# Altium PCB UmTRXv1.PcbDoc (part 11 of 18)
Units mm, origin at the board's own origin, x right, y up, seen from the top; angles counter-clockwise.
Board outline 172 x 113 mm, 6 copper layers (Top Layer, GND, MidLayer1, Mid-Layer 2, InternalPlane2, Bottom Layer); 766 components, 613 nets, 3008 pads, 1360 vias.
Unrouted connection lines stored in the file: 2.
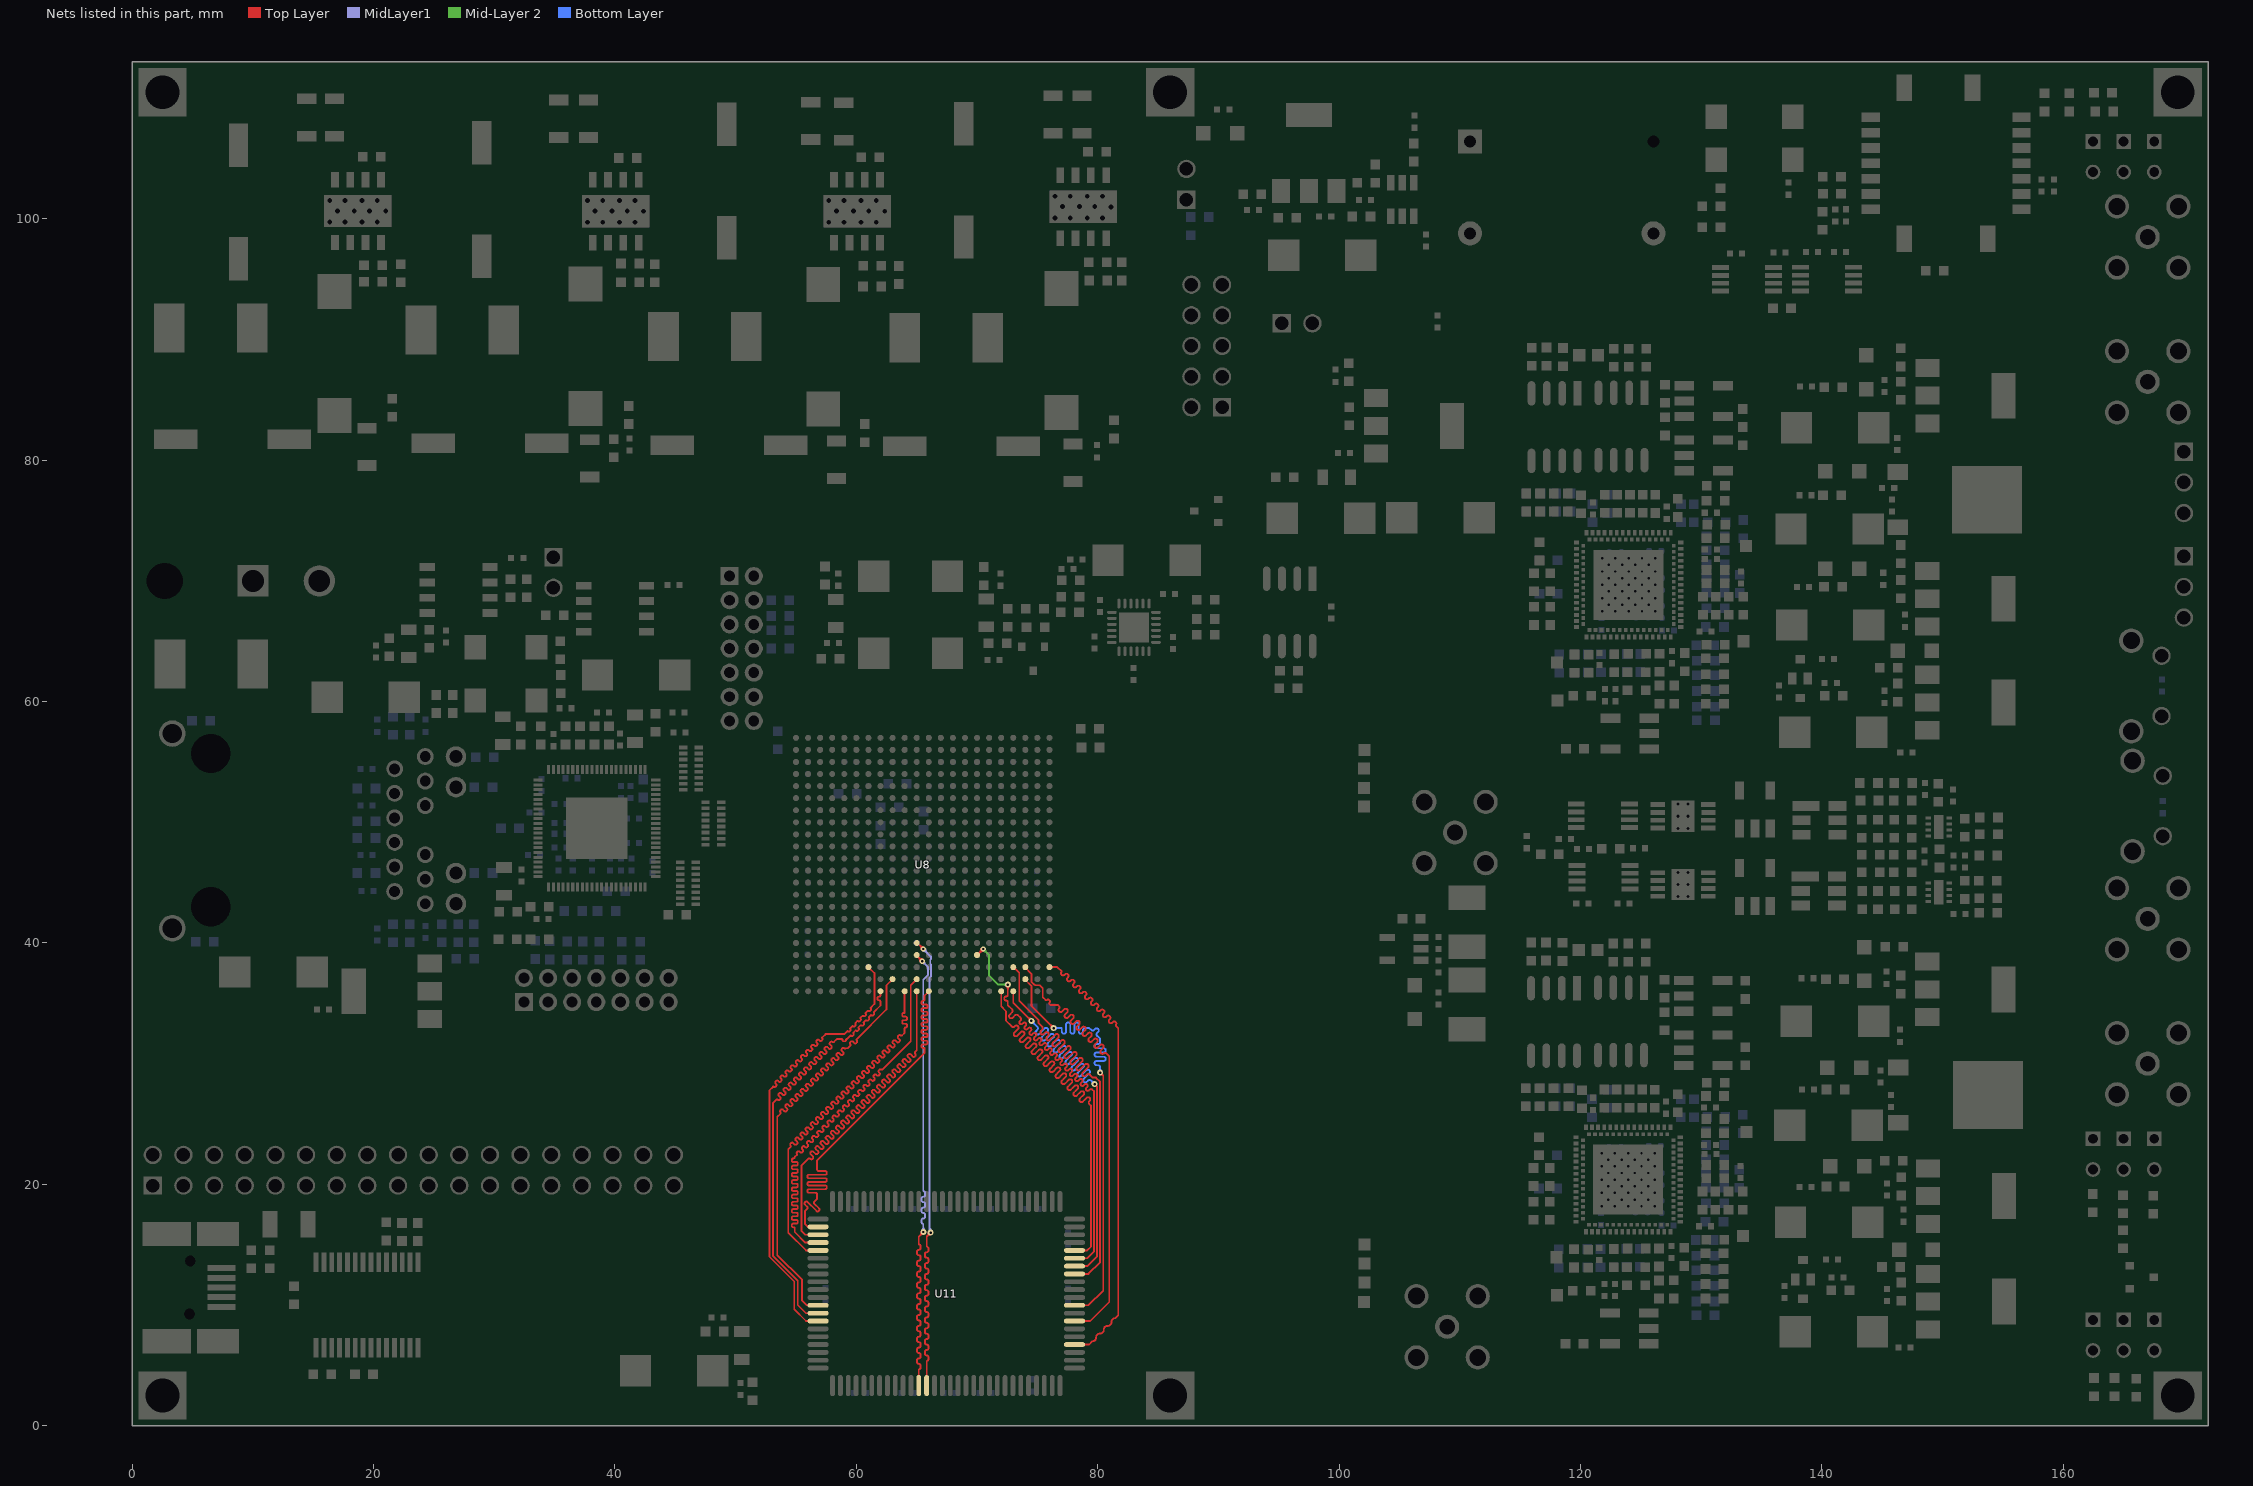
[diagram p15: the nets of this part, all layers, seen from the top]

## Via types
v1: diameter 0.45, hole 0.2, Top Layer to Bottom Layer, tented both sides, 554 vias
v2: diameter 0.5, hole 0.2, Top Layer to Bottom Layer, tented both sides, 468 vias
v3: diameter 0.7, hole 0.3, Top Layer to Bottom Layer, tented both sides, 206 vias
v4: diameter 0.4, hole 0.2, Top Layer to Bottom Layer, tented both sides, 82 vias
v5: diameter 0.8, hole 0.3, Top Layer to Bottom Layer, tented both sides, 16 vias
v6: diameter 0.6, hole 0.25, Top Layer to Bottom Layer, tented both sides, 16 vias
v7: diameter 0.5, hole 0.3, Top Layer to Bottom Layer, tented both sides, 8 vias
v8: diameter 0.7, hole 0.3, Top Layer to Bottom Layer, 4 vias
v9: diameter 0.6, hole 0.3, Top Layer to Bottom Layer, tented both sides, 4 vias
v10: diameter 0.5, hole 0.2, Top Layer to Bottom Layer, 2 vias

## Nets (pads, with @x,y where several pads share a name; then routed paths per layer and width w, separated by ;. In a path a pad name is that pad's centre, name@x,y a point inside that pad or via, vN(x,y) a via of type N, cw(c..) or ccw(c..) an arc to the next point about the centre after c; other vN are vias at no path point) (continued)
RAM_A13: U8.C16 U11.44 | length 40.9
  Top Layer w0.15: 54.158,29.2 54.179,29.179 54.2,29.158 cw(c54.115,29.073) 54.2,28.988 54.158,28.946 cw(c54.073,29.03) 53.988,28.946 53.946,28.988 ccw(c53.861,28.903) 53.776,28.988 53.733,28.946 ccw(c53.818,28.861) 53.733,28.776 53.776,28.733 cw(c53.691,28.649) 53.776,28.564 53.733,28.521 cw(c53.649,28.606) 53.564,28.521 53.521,28.564 ccw(c53.436,28.479) 53.352,28.564 53.309,28.521 ccw(c53.394,28.436) 53.309,28.352 53.352,28.309 cw(c53.267,28.224) 53.352,28.14 53.309,28.097 cw(c53.224,28.182) 53.139,28.097 ccw(c53.118,28.076) 53.097,28.097 52.8,27.8 52.8,13.996 54.85,11.946 54.85,9.65 55.825,8.675 U11.44@56.825,8.675 ; 54.157,29.2 cw(c54.242,29.285) 54.158,29.37 54.2,29.412 ; 54.2,29.412 cw(c54.285,29.327) 54.37,29.412 54.412,29.37 ccw(c54.497,29.455) 54.582,29.37 54.624,29.412 ; 54.624,29.836 cw(c54.709,29.752) 54.794,29.836 ; 54.624,29.836 54.582,29.794 ccw(c54.667,29.709) 54.582,29.624 54.624,29.582 cw(c54.539,29.497) 54.624,29.412 ; 54.794,29.836 54.836,29.794 ccw(c54.921,29.879) 55.006,29.794 55.049,29.836 ccw(c54.964,29.921) 55.049,30.006 ; 55.049,30.006 55.006,30.049 cw(c55.091,30.133) 55.006,30.218 55.049,30.261 ; 55.049,30.261 cw(c55.133,30.176) 55.218,30.261 55.261,30.218 ccw(c55.346,30.303) 55.43,30.218 55.473,30.261 ccw(c55.388,30.346) 55.473,30.43 55.43,30.473 cw(c55.515,30.558) 55.43,30.642 55.473,30.685 cw(c55.558,30.6) 55.643,30.685 55.685,30.643 ccw(c55.77,30.727) 55.855,30.642 55.897,30.685 ccw(c55.812,30.77) 55.897,30.855 55.876,30.876 55.855,30.897 cw(c55.94,30.982) 55.855,31.067 55.897,31.109 cw(c55.982,31.024) 56.067,31.109 56.109,31.067 ccw(c56.194,31.152) 56.279,31.067 56.321,31.109 ccw(c56.237,31.194) 56.321,31.279 56.279,31.321 cw(c56.364,31.406) 56.279,31.491 56.321,31.534 cw(c56.406,31.449) 56.491,31.534 56.534,31.491 ccw(c56.618,31.576) 56.703,31.491 56.746,31.534 ccw(c56.661,31.618) 56.746,31.703 56.703,31.746 cw(c56.788,31.831) 56.703,31.915 56.746,31.958 cw(c56.83,31.873) 56.915,31.958 56.958,31.915 ccw(c57.043,32) 57.127,31.915 57.17,31.958 ccw(c57.085,32.043) 57.17,32.127 cw(c57.191,32.149) 57.17,32.17 57.45,32.45 59,32.45 59.235,32.685 cw(c59.256,32.664) 59.277,32.685 ccw(c59.362,32.77) 59.447,32.685 59.489,32.727 ccw(c59.405,32.812) 59.489,32.897 cw(c59.511,32.918) 59.489,32.939 59.659,33.109 ; 59.659,33.109 cw(c59.68,33.088) 59.702,33.109 ccw(c59.786,33.194) 59.871,33.109 59.914,33.152 ccw(c59.829,33.236) 59.914,33.321 cw(c59.935,33.342) 59.914,33.364 60.083,33.533 cw(c60.105,33.512) 60.126,33.533 ccw(c60.211,33.618) 60.295,33.533 60.338,33.576 ccw(c60.253,33.661) 60.338,33.746 cw(c60.359,33.767) 60.338,33.788 60.508,33.958 cw(c60.529,33.936) 60.55,33.958 ccw(c60.635,34.042) 60.72,33.958 60.762,34 ccw(c60.677,34.085) 60.762,34.17 cw(c60.783,34.191) 60.762,34.212 60.932,34.382 cw(c60.953,34.361) 60.974,34.382 ccw(c61.059,34.467) 61.144,34.382 ; U8.C16@61,38 61.5,37.5 61.5,34.95 61.186,34.636 ccw(c61.208,34.615) 61.186,34.594 cw(c61.102,34.509) 61.186,34.424 61.144,34.382
RAM_A14: U8.A13 U11.35 | length 40.9
  Top Layer w0.15: 54.549,23.382 ccw(c54.634,23.297) 54.549,23.213 cw(c54.493,23.156) 54.549,23.099 54.35,22.9 54.35,16 55.825,14.525 U11.35@56.825,14.525 ; 54.549,23.382 54.592,23.425 cw(c54.677,23.34) 54.761,23.425 54.818,23.368 54.875,23.312 ccw(c54.96,23.396) 55.044,23.311 55.087,23.354 ccw(c55.002,23.439) 55.087,23.524 54.974,23.637 ; 54.974,23.637 cw(c55.059,23.722) 54.974,23.806 ; 54.974,23.807 55.016,23.849 cw(c55.101,23.764) 55.186,23.849 55.242,23.792 55.299,23.736 ccw(c55.384,23.821) 55.469,23.736 55.511,23.778 ccw(c55.426,23.863) 55.511,23.948 55.455,24.005 55.398,24.061 cw(c55.483,24.146) 55.398,24.231 ; 55.398,24.231 55.44,24.273 cw(c55.525,24.188) 55.61,24.273 55.667,24.217 55.723,24.16 ccw(c55.808,24.245) 55.893,24.16 55.935,24.203 ccw(c55.851,24.287) 55.935,24.372 55.879,24.429 55.822,24.485 cw(c55.907,24.57) 55.822,24.655 55.865,24.698 cw(c55.95,24.613) 56.034,24.698 56.091,24.641 56.148,24.584 ccw(c56.232,24.669) 56.317,24.584 56.36,24.627 ; 56.36,24.627 ccw(c56.275,24.712) 56.36,24.797 56.303,24.853 56.247,24.91 cw(c56.331,24.995) 56.246,25.079 56.289,25.122 cw(c56.374,25.037) 56.459,25.122 56.515,25.065 56.572,25.009 ccw(c56.657,25.094) 56.741,25.009 56.784,25.051 ; 56.784,25.051 ccw(c56.699,25.136) 56.784,25.221 56.671,25.334 cw(c56.756,25.419) 56.671,25.504 56.713,25.546 cw(c56.798,25.461) 56.883,25.546 56.94,25.49 56.996,25.433 ccw(c57.081,25.518) 57.166,25.433 ; 57.166,25.433 57.208,25.475 ccw(c57.123,25.56) 57.208,25.645 57.152,25.702 57.095,25.758 cw(c57.18,25.843) 57.095,25.928 57.137,25.97 cw(c57.222,25.885) 57.307,25.97 57.364,25.914 57.42,25.857 ccw(c57.505,25.942) 57.59,25.857 ; 57.59,25.857 57.632,25.9 ccw(c57.548,25.984) 57.633,26.069 57.576,26.126 57.519,26.182 cw(c57.604,26.267) 57.519,26.352 57.562,26.395 cw(c57.647,26.31) 57.731,26.395 57.788,26.338 57.845,26.281 ccw(c57.929,26.366) 58.014,26.281 58.057,26.324 ccw(c57.972,26.409) 58.057,26.494 58,26.55 57.944,26.607 cw(c58.028,26.692) 57.943,26.776 57.986,26.819 ; 57.986,26.819 cw(c58.071,26.734) 58.156,26.819 58.212,26.762 58.269,26.706 ccw(c58.354,26.791) 58.438,26.706 58.481,26.748 ccw(c58.396,26.833) 58.481,26.918 58.424,26.974 58.368,27.031 cw(c58.453,27.116) 58.368,27.201 58.41,27.243 ; 58.41,27.243 cw(c58.495,27.158) 58.58,27.243 58.637,27.187 58.693,27.13 ccw(c58.778,27.215) 58.863,27.13 58.905,27.172 ccw(c58.82,27.257) 58.905,27.342 58.849,27.399 58.792,27.455 cw(c58.877,27.54) 58.792,27.625 58.835,27.667 cw(c58.919,27.583) 59.004,27.667 59.061,27.611 59.117,27.554 ccw(c59.202,27.639) 59.287,27.554 59.33,27.597 ccw(c59.245,27.682) 59.33,27.766 ; 59.33,27.766 59.273,27.823 59.216,27.88 cw(c59.301,27.964) 59.216,28.049 59.259,28.092 cw(c59.344,28.007) 59.428,28.092 59.542,27.979 ; 59.542,27.978 ccw(c59.627,28.063) 59.711,27.978 ; 59.711,27.979 59.754,28.021 ccw(c59.669,28.106) 59.754,28.191 59.697,28.247 59.641,28.304 cw(c59.726,28.389) 59.64,28.473 59.683,28.516 cw(c59.768,28.431) 59.853,28.516 59.909,28.459 59.966,28.403 ccw(c60.051,28.488) 60.135,28.403 ; 60.136,28.403 60.178,28.445 ; 60.178,28.445 ccw(c60.093,28.53) 60.178,28.615 60.121,28.671 60.065,28.728 cw(c60.15,28.813) 60.065,28.898 60.107,28.94 cw(c60.192,28.855) 60.277,28.94 60.334,28.884 60.39,28.827 ccw(c60.475,28.912) 60.56,28.827 60.602,28.869 ; 60.602,28.87 ccw(c60.517,28.954) 60.602,29.039 60.546,29.096 60.489,29.152 cw(c60.574,29.237) 60.489,29.322 60.532,29.364 cw(c60.616,29.28) 60.701,29.364 60.758,29.308 60.814,29.251 ccw(c60.899,29.336) 60.984,29.251 61.027,29.294 ccw(c60.942,29.379) 61.027,29.463 60.97,29.52 60.913,29.577 cw(c60.998,29.661) 60.913,29.746 60.956,29.789 cw(c61.041,29.704) 61.125,29.789 61.239,29.676 ccw(c61.324,29.76) 61.408,29.675 61.451,29.718 ccw(c61.366,29.803) 61.451,29.888 61.394,29.944 61.338,30.001 ; 61.338,30.001 cw(c61.423,30.086) 61.338,30.171 61.38,30.213 cw(c61.465,30.128) 61.55,30.213 61.606,30.156 61.663,30.1 ccw(c61.748,30.185) 61.833,30.1 61.875,30.142 ccw(c61.79,30.227) 61.875,30.312 61.819,30.369 61.762,30.425 cw(c61.847,30.51) 61.762,30.595 ; 61.762,30.595 61.804,30.637 cw(c61.889,30.552) 61.974,30.637 ; 61.974,30.637 62.031,30.581 62.087,30.524 ccw(c62.172,30.609) 62.257,30.524 62.299,30.567 ccw(c62.215,30.651) 62.299,30.736 62.243,30.793 62.186,30.849 cw(c62.271,30.934) 62.186,31.019 62.229,31.062 cw(c62.314,30.977) 62.398,31.062 62.455,31.005 62.512,30.948 ccw(c62.596,31.033) 62.681,30.948 62.724,30.991 ; 62.724,30.991 ccw(c62.639,31.076) 62.724,31.16 62.667,31.217 62.61,31.274 cw(c62.695,31.358) 62.61,31.443 62.653,31.486 cw(c62.738,31.401) 62.823,31.486 62.879,31.429 62.936,31.373 ccw(c63.021,31.457) 63.105,31.372 63.148,31.415 ; 63.148,31.415 ccw(c63.063,31.5) 63.148,31.585 63.091,31.641 63.035,31.698 cw(c63.12,31.783) 63.035,31.868 63.077,31.91 cw(c63.162,31.825) 63.247,31.91 63.303,31.853 63.36,31.797 ccw(c63.445,31.882) 63.53,31.797 ; 63.53,31.797 63.572,31.839 ccw(c63.487,31.924) 63.572,32.009 63.516,32.066 63.459,32.122 cw(c63.544,32.207) 63.459,32.292 63.501,32.334 cw(c63.586,32.249) 63.671,32.334 ccw(c63.728,32.391) 63.784,32.334 64,32.55 64,32.92 cw(c64.08,32.92) 64.08,33 ccw(c64.08,33.12) 64.2,33.12 64.2,33.18 ccw(c64.08,33.18) 64.08,33.3 63.92,33.3 cw(c63.92,33.42) 63.8,33.42 63.8,33.48 cw(c63.92,33.48) 63.92,33.6 64.08,33.6 ccw(c64.08,33.72) 64.2,33.72 64.2,33.78 ccw(c64.08,33.78) 64.08,33.9 63.92,33.9 cw(c63.92,34.02) 63.8,34.02 63.8,34.08 cw(c63.92,34.08) 63.92,34.2 63.95,34.2 ccw(c63.95,34.25) 64,34.25 U8.A13@64,36
RAM_A15: U8.B12 U11.34 | length 41.3
  Top Layer w0.15: 55.552,22.709 55.509,22.667 cw(c55.424,22.752) 55.339,22.667 55.297,22.709 ccw(c55.212,22.625) 55.127,22.709 55.085,22.667 ccw(c55.17,22.582) 55.085,22.497 cw(c55.064,22.476) 55.085,22.455 54.9,22.27 cw(c54.78,22.27) 54.78,22.15 54.77,22.15 ccw(c54.77,22.03) 54.65,22.03 54.65,21.97 ccw(c54.77,21.97) 54.77,21.85 55.03,21.85 cw(c55.03,21.73) 55.15,21.73 55.15,21.67 cw(c55.03,21.67) 55.03,21.55 54.77,21.55 ccw(c54.77,21.43) 54.65,21.43 54.65,21.37 ccw(c54.77,21.37) 54.77,21.25 55.03,21.25 cw(c55.03,21.13) 55.15,21.13 55.15,21.07 cw(c55.03,21.07) 55.03,20.95 54.77,20.95 ccw(c54.77,20.83) 54.65,20.83 54.65,20.77 ccw(c54.77,20.77) 54.77,20.65 55.03,20.65 cw(c55.03,20.53) 55.15,20.53 55.15,20.47 cw(c55.03,20.47) 55.03,20.35 54.77,20.35 ccw(c54.77,20.23) 54.65,20.23 54.65,20.17 ccw(c54.77,20.17) 54.77,20.05 55.03,20.05 cw(c55.03,19.93) 55.15,19.93 55.15,19.87 cw(c55.03,19.87) 55.03,19.75 54.77,19.75 ccw(c54.77,19.63) 54.65,19.63 54.65,19.57 ccw(c54.77,19.57) 54.77,19.45 55.03,19.45 cw(c55.03,19.33) 55.15,19.33 55.15,19.27 cw(c55.03,19.27) 55.03,19.15 54.77,19.15 ccw(c54.77,19.03) 54.65,19.03 54.65,18.97 ccw(c54.77,18.97) 54.77,18.85 55.03,18.85 cw(c55.03,18.73) 55.15,18.73 55.15,18.67 cw(c55.03,18.67) 55.03,18.55 54.77,18.55 ccw(c54.77,18.43) 54.65,18.43 54.65,18.37 ccw(c54.77,18.37) 54.77,18.25 55.03,18.25 cw(c55.03,18.13) 55.15,18.13 55.15,18.07 cw(c55.03,18.07) 55.03,17.95 54.77,17.95 ccw(c54.77,17.83) 54.65,17.83 54.65,17.77 ccw(c54.77,17.77) 54.77,17.65 55.03,17.65 cw(c55.03,17.53) 55.15,17.53 55.15,17.47 cw(c55.03,17.47) 55.03,17.35 54.77,17.35 ccw(c54.77,17.23) 54.65,17.23 54.65,17.17 ccw(c54.77,17.17) 54.77,17.05 55.03,17.05 cw(c55.03,16.93) 55.15,16.93 55.15,16.87 cw(c55.03,16.87) 55.03,16.75 54.77,16.75 ccw(c54.77,16.63) 54.65,16.63 54.65,16.57 ccw(c54.77,16.57) 54.77,16.45 54.78,16.45 cw(c54.78,16.33) 54.9,16.33 54.9,16.05 55.775,15.175 U11.34@56.825,15.175 ; 55.552,23.134 55.509,23.091 ccw(c55.594,23.006) 55.509,22.922 55.552,22.879 cw(c55.467,22.794) 55.552,22.71 ; 55.552,23.134 cw(c55.636,23.049) 55.721,23.134 55.764,23.091 ccw(c55.849,23.176) 55.933,23.091 55.976,23.134 ccw(c55.891,23.219) 55.976,23.303 55.933,23.346 cw(c56.018,23.431) 55.933,23.515 55.976,23.558 cw(c56.061,23.473) 56.145,23.558 56.188,23.515 ccw(c56.273,23.6) 56.357,23.515 56.4,23.558 ccw(c56.315,23.643) 56.4,23.727 56.379,23.749 56.358,23.77 cw(c56.442,23.855) 56.358,23.94 56.4,23.982 cw(c56.485,23.897) 56.57,23.982 56.612,23.94 ccw(c56.697,24.025) 56.782,23.94 56.824,23.982 ccw(c56.739,24.067) 56.824,24.152 56.782,24.194 cw(c56.867,24.279) 56.782,24.364 56.824,24.406 cw(c56.909,24.322) 56.994,24.406 57.036,24.364 ccw(c57.121,24.449) 57.206,24.364 57.249,24.406 ccw(c57.164,24.491) 57.249,24.576 ; 57.206,24.788 ccw(c57.291,24.703) 57.206,24.619 57.249,24.576 ; 57.206,24.788 57.249,24.831 cw(c57.333,24.746) 57.418,24.831 57.461,24.788 ccw(c57.546,24.873) 57.63,24.788 57.673,24.831 ccw(c57.588,24.916) 57.673,25 57.63,25.043 cw(c57.715,25.128) 57.63,25.212 57.673,25.255 cw(c57.758,25.17) 57.843,25.255 57.885,25.213 ccw(c57.97,25.297) 58.055,25.212 ; 58.055,25.213 58.097,25.255 ccw(c58.012,25.34) 58.097,25.425 58.076,25.446 58.055,25.467 cw(c58.14,25.552) 58.055,25.637 58.097,25.679 cw(c58.182,25.594) 58.267,25.679 58.309,25.637 ccw(c58.394,25.722) 58.479,25.637 58.521,25.679 ccw(c58.437,25.764) 58.521,25.849 58.479,25.891 cw(c58.564,25.976) 58.479,26.061 ; 58.479,26.061 58.521,26.104 cw(c58.606,26.019) 58.691,26.104 58.734,26.061 ccw(c58.818,26.146) 58.903,26.061 ; 58.903,26.485 ccw(c58.988,26.4) 58.903,26.316 58.946,26.273 cw(c58.861,26.188) 58.946,26.103 58.903,26.061 ; 58.903,26.485 58.946,26.528 cw(c59.03,26.443) 59.115,26.528 59.158,26.485 ccw(c59.243,26.57) 59.327,26.485 59.37,26.528 ccw(c59.285,26.613) 59.37,26.697 59.327,26.74 cw(c59.412,26.825) 59.327,26.909 59.37,26.952 cw(c59.455,26.867) 59.54,26.952 59.582,26.91 ccw(c59.667,26.994) 59.752,26.909 59.794,26.952 ccw(c59.709,27.037) 59.794,27.122 59.752,27.164 cw(c59.837,27.249) 59.752,27.334 59.794,27.376 cw(c59.879,27.291) 59.964,27.376 60.006,27.334 ccw(c60.091,27.419) 60.176,27.334 60.218,27.376 ccw(c60.134,27.461) 60.218,27.546 60.176,27.588 cw(c60.261,27.673) 60.176,27.758 60.218,27.801 ; 60.219,27.801 cw(c60.303,27.716) 60.388,27.801 60.431,27.758 ccw(c60.515,27.843) 60.6,27.758 60.643,27.801 ; 60.643,27.801 ccw(c60.558,27.885) 60.643,27.97 60.6,28.013 cw(c60.685,28.098) 60.6,28.182 60.643,28.225 cw(c60.728,28.14) 60.812,28.225 ; 60.812,28.225 60.834,28.204 60.855,28.182 ccw(c60.94,28.267) 61.025,28.182 61.067,28.225 ; 61.067,28.225 ccw(c60.982,28.31) 61.067,28.395 61.025,28.437 cw(c61.109,28.522) 61.024,28.607 61.067,28.649 cw(c61.152,28.564) 61.237,28.649 61.279,28.607 ccw(c61.364,28.692) 61.449,28.607 61.491,28.649 ccw(c61.406,28.734) 61.491,28.819 61.449,28.861 cw(c61.534,28.946) 61.449,29.031 61.491,29.073 cw(c61.576,28.988) 61.661,29.074 61.703,29.031 ccw(c61.788,29.116) 61.873,29.031 61.915,29.073 ; 61.915,29.498 61.873,29.455 ccw(c61.958,29.37) 61.873,29.285 61.915,29.243 cw(c61.831,29.158) 61.916,29.073 ; 61.916,29.498 cw(c62,29.413) 62.085,29.498 ccw(c62.106,29.519) 62.128,29.498 64.5,31.87 64.5,36.5 U8.B12@65,37
RAM_A16: U8.A12 U11.33 | length 41.5
  Top Layer w0.15: 56.358,22.104 cw(c56.273,22.189) 56.188,22.105 56.181,22.112 ccw(c56.097,22.027) 56.012,22.112 55.45,21.55 55.45,16.15 55.775,15.825 U11.33@56.825,15.825 ; 56.358,22.105 56.401,22.147 ccw(c56.316,22.232) 56.401,22.317 56.309,22.409 56.217,22.501 cw(c56.302,22.585) 56.217,22.67 56.259,22.713 cw(c56.344,22.628) 56.429,22.713 56.613,22.529 ccw(c56.698,22.614) 56.782,22.529 56.825,22.571 ccw(c56.74,22.656) 56.825,22.741 56.641,22.925 cw(c56.726,23.01) 56.641,23.094 56.683,23.137 cw(c56.768,23.052) 56.853,23.137 57.037,22.953 ccw(c57.122,23.038) 57.207,22.953 ; 57.108,23.561 57.065,23.519 ccw(c57.15,23.434) 57.065,23.349 57.249,23.165 ; 57.108,23.561 cw(c57.193,23.476) 57.277,23.561 ; 57.207,22.953 57.249,22.996 ccw(c57.164,23.08) 57.249,23.165 ; 57.277,23.561 57.369,23.469 57.461,23.377 ; 57.461,23.377 ccw(c57.546,23.462) 57.631,23.377 57.673,23.42 ccw(c57.589,23.505) 57.673,23.59 57.49,23.773 ; 57.489,23.774 cw(c57.574,23.858) 57.49,23.943 57.532,23.986 cw(c57.617,23.901) 57.702,23.986 ; 57.702,23.986 57.886,23.802 ccw(c57.97,23.887) 58.055,23.802 58.098,23.844 ccw(c58.013,23.929) 58.098,24.014 58.006,24.106 57.914,24.198 ; 57.914,24.198 cw(c57.999,24.283) 57.914,24.367 ; 57.914,24.367 57.956,24.41 cw(c58.041,24.325) 58.126,24.41 ; 58.126,24.41 58.31,24.226 ccw(c58.395,24.311) 58.479,24.226 58.522,24.268 ccw(c58.437,24.353) 58.522,24.438 58.43,24.53 58.338,24.622 ; 58.338,24.622 cw(c58.423,24.707) 58.338,24.792 58.38,24.834 cw(c58.465,24.749) 58.55,24.834 58.734,24.65 ccw(c58.819,24.735) 58.904,24.65 58.946,24.693 ccw(c58.861,24.777) 58.946,24.862 ; 58.946,24.862 58.762,25.046 cw(c58.847,25.131) 58.762,25.216 58.805,25.258 cw(c58.89,25.173) 58.974,25.258 59.066,25.166 59.158,25.074 ; 59.158,25.074 ccw(c59.243,25.159) 59.328,25.074 59.37,25.117 ; 59.371,25.117 ccw(c59.286,25.202) 59.37,25.287 59.187,25.47 cw(c59.271,25.555) 59.187,25.64 59.229,25.683 cw(c59.314,25.598) 59.399,25.683 59.583,25.499 ccw(c59.667,25.584) 59.752,25.499 59.795,25.541 ccw(c59.71,25.626) 59.795,25.711 59.703,25.803 59.611,25.895 cw(c59.696,25.98) 59.611,26.064 59.653,26.107 cw(c59.738,26.022) 59.823,26.107 60.007,25.923 ccw(c60.092,26.008) 60.177,25.923 60.219,25.965 ; 60.219,25.966 ccw(c60.134,26.05) 60.219,26.135 60.127,26.227 60.035,26.319 cw(c60.12,26.404) 60.035,26.489 60.078,26.531 cw(c60.162,26.446) 60.247,26.531 60.431,26.347 ccw(c60.516,26.432) 60.601,26.347 60.643,26.39 ccw(c60.558,26.475) 60.643,26.559 60.459,26.743 cw(c60.544,26.828) 60.459,26.913 ; 60.459,26.913 60.502,26.955 cw(c60.587,26.871) 60.671,26.956 60.763,26.863 60.855,26.772 ccw(c60.94,26.856) 61.025,26.771 61.067,26.814 ccw(c60.983,26.899) 61.068,26.983 60.884,27.167 cw(c60.968,27.252) 60.884,27.337 60.926,27.38 cw(c61.011,27.295) 61.096,27.38 61.28,27.196 ccw(c61.364,27.281) 61.449,27.196 61.492,27.238 ccw(c61.407,27.323) 61.492,27.408 61.308,27.592 cw(c61.393,27.677) 61.308,27.761 61.35,27.804 cw(c61.435,27.719) 61.52,27.804 61.704,27.62 ccw(c61.789,27.705) 61.874,27.62 61.916,27.662 ccw(c61.831,27.747) 61.916,27.832 61.824,27.924 61.732,28.016 cw(c61.817,28.101) 61.732,28.186 61.775,28.228 cw(c61.859,28.143) 61.944,28.228 62.128,28.044 ccw(c62.213,28.129) 62.298,28.044 62.34,28.087 ccw(c62.255,28.172) 62.34,28.256 62.156,28.44 cw(c62.241,28.525) 62.156,28.61 62.199,28.652 cw(c62.284,28.568) 62.368,28.653 62.46,28.56 62.552,28.469 ccw(c62.637,28.553) 62.722,28.468 ; 62.722,28.469 62.765,28.511 ccw(c62.68,28.596) 62.765,28.681 62.581,28.865 cw(c62.666,28.949) 62.581,29.034 62.623,29.077 cw(c62.708,28.992) 62.793,29.077 62.885,28.985 62.977,28.893 ccw(c63.062,28.978) 63.146,28.893 63.189,28.935 ccw(c63.104,29.02) 63.189,29.105 63.005,29.289 cw(c63.09,29.374) 63.005,29.458 63.047,29.501 cw(c63.132,29.416) 63.217,29.501 63.401,29.317 ccw(c63.486,29.402) 63.57,29.317 ; 63.571,29.317 63.613,29.36 ccw(c63.528,29.444) 63.613,29.529 ; 63.613,29.529 63.521,29.621 63.429,29.713 cw(c63.514,29.798) 63.429,29.883 63.472,29.925 cw(c63.556,29.84) 63.641,29.925 63.825,29.741 ; 63.825,29.741 ccw(c63.91,29.826) 63.995,29.741 64.037,29.784 ccw(c63.952,29.869) 64.037,29.953 63.853,30.137 cw(c63.938,30.222) 63.853,30.307 63.896,30.349 ; 63.896,30.35 cw(c63.981,30.265) 64.066,30.349 64.249,30.166 ccw(c64.334,30.25) 64.419,30.165 64.462,30.208 ccw(c64.377,30.293) 64.462,30.378 64.278,30.562 ; 64.278,30.562 cw(c64.363,30.646) 64.278,30.731 64.32,30.774 cw(c64.405,30.689) 64.49,30.774 ; 64.49,30.774 64.582,30.682 64.674,30.59 ccw(c64.759,30.675) 64.843,30.59 64.886,30.632 ccw(c64.801,30.717) 64.886,30.802 64.879,30.809 cw(c64.964,30.894) 64.879,30.979 65,31.1 U8.A12@65,36
RAM_A17: U8.A11 U11.32 | length 41
  Top Layer w0.15: U11.32@56.825,16.475 55.975,16.475 55.75,16.7 55.75,17.8 55.925,17.975 ccw(c55.842,18.058) 55.925,18.14 55.735,18.33 cw(c55.82,18.415) 55.735,18.5 55.778,18.542 cw(c55.862,18.457) 55.947,18.542 56.701,17.789 ccw(c56.785,17.874) 56.87,17.789 56.913,17.831 ccw(c56.828,17.916) 56.913,18.001 56.517,18.397 cw(c56.602,18.482) 56.517,18.567 56.75,18.8 56.75,19.18 ccw(c56.63,19.18) 56.63,19.3 56.07,19.3 cw(c56.07,19.42) 55.95,19.42 55.95,19.48 cw(c56.07,19.48) 56.07,19.6 57.43,19.6 ccw(c57.43,19.72) 57.55,19.72 57.55,19.78 ccw(c57.43,19.78) 57.43,19.9 56.07,19.9 cw(c56.07,20.02) 55.95,20.02 55.95,20.08 cw(c56.07,20.08) 56.07,20.2 57.43,20.2 ccw(c57.43,20.32) 57.55,20.32 57.55,20.38 ccw(c57.43,20.38) 57.43,20.5 56.07,20.5 cw(c56.07,20.62) 55.95,20.62 55.95,20.68 cw(c56.07,20.68) 56.07,20.8 57.43,20.8 ccw(c57.43,20.92) 57.55,20.92 57.55,20.98 ccw(c57.43,20.98) 57.43,21.1 56.87,21.1 cw(c56.87,21.22) 56.75,21.22 56.75,22 65.65,30.9 65.65,31.3 65.52,31.3 cw(c65.52,31.42) 65.4,31.42 65.4,31.48 cw(c65.52,31.48) 65.52,31.6 65.78,31.6 ccw(c65.78,31.72) 65.9,31.72 65.9,31.78 ccw(c65.78,31.78) 65.78,31.9 65.52,31.9 cw(c65.52,32.02) 65.4,32.02 65.4,32.08 cw(c65.52,32.08) 65.52,32.2 65.78,32.2 ccw(c65.78,32.32) 65.9,32.32 65.9,32.38 ccw(c65.78,32.38) 65.78,32.5 65.52,32.5 cw(c65.52,32.62) 65.4,32.62 65.4,32.68 cw(c65.52,32.68) 65.52,32.8 65.78,32.8 ccw(c65.78,32.92) 65.9,32.92 65.9,32.98 ccw(c65.78,32.98) 65.78,33.1 65.52,33.1 cw(c65.52,33.22) 65.4,33.22 65.4,33.28 cw(c65.52,33.28) 65.52,33.4 65.78,33.4 ccw(c65.78,33.52) 65.9,33.52 65.9,33.58 ccw(c65.78,33.58) 65.78,33.7 65.52,33.7 cw(c65.52,33.82) 65.4,33.82 65.4,33.88 cw(c65.52,33.88) 65.52,34 65.78,34 ccw(c65.78,34.12) 65.9,34.12 65.9,34.18 ccw(c65.78,34.18) 65.78,34.3 65.52,34.3 cw(c65.52,34.42) 65.4,34.42 65.4,34.48 cw(c65.52,34.48) 65.52,34.6 65.78,34.6 ccw(c65.78,34.72) 65.9,34.72 65.9,34.78 ccw(c65.78,34.78) 65.78,34.9 65.52,34.9 cw(c65.52,35.02) 65.4,35.02 65.4,35.08 cw(c65.52,35.08) 65.52,35.2 65.53,35.2 ccw(c65.53,35.32) 65.65,35.32 65.65,35.65 U8.A11@66,36
RAM_A18: U8.C1 U11.84 | length 41
  Top Layer w0.15: U8.C1@76,38 76.65,38 77.004,37.646 cw(c76.986,37.629) 77.004,37.611 ccw(c77.127,37.487) 77.004,37.364 ccw(c77.127,37.487) 77.251,37.364 77.286,37.399 cw(c77.41,37.275) 77.534,37.399 cw(c77.41,37.275) 77.534,37.151 77.499,37.116 ccw(c77.622,36.992) 77.499,36.869 ccw(c77.622,36.992) 77.746,36.869 77.764,36.886 77.781,36.904 cw(c77.905,36.78) 78.029,36.904 cw(c77.905,36.78) 78.029,36.657 78.011,36.639 77.993,36.621 ccw(c78.117,36.497) 77.993,36.374 ccw(c78.117,36.497) 78.241,36.374 78.276,36.409 cw(c78.4,36.285) 78.524,36.409 cw(c78.4,36.285) 78.524,36.162 78.488,36.126 ccw(c78.612,36.002) 78.488,35.879 ccw(c78.612,36.002) 78.736,35.879 78.771,35.914 cw(c78.895,35.79) 79.019,35.914 cw(c78.895,35.79) 79.019,35.667 79.001,35.649 78.983,35.631 ccw(c79.107,35.507) 78.983,35.384 ccw(c79.107,35.507) 79.231,35.384 79.249,35.401 79.266,35.419 cw(c79.39,35.295) 79.514,35.419 cw(c79.39,35.295) 79.514,35.172 79.478,35.136 ccw(c79.602,35.012) 79.478,34.889 ccw(c79.602,35.012) 79.726,34.889 79.761,34.924 cw(c79.885,34.8) 80.009,34.924 cw(c79.885,34.8) 80.009,34.677 79.991,34.659 79.973,34.641 ccw(c80.097,34.518) 79.973,34.394 ccw(c80.097,34.518) 80.221,34.394 80.239,34.411 80.256,34.429 cw(c80.38,34.305) 80.504,34.429 cw(c80.38,34.305) 80.504,34.182 80.468,34.146 ccw(c80.592,34.023) 80.468,33.899 ccw(c80.592,34.023) 80.716,33.899 80.751,33.934 cw(c80.875,33.81) 80.999,33.934 cw(c80.875,33.81) 80.999,33.687 80.963,33.651 ccw(c81.087,33.528) 80.963,33.404 ccw(c81.087,33.528) 81.211,33.404 81.229,33.421 81.246,33.439 cw(c81.37,33.315) 81.494,33.439 cw(c81.37,33.315) 81.494,33.192 ccw(c81.511,33.174) 81.494,33.156 81.7,32.95 81.7,9.15 81.459,8.909 ccw(c81.444,8.606) 81.141,8.591 cw(c80.838,8.576) 80.823,8.273 ccw(c80.807,7.97) 80.505,7.955 cw(c80.202,7.939) 80.186,7.636 ccw(c80.171,7.334) 79.868,7.318 cw(c79.565,7.303) 79.55,7 79.275,6.725 U11.84@78.075,6.725
RAM_A19: U8.A15 U11.43 | length 40.8
  Top Layer w0.15: 54.04,27.973 53.998,27.931 ccw(c54.083,27.846) 53.998,27.761 54.055,27.705 54.111,27.648 cw(c54.026,27.563) 54.111,27.478 54.069,27.436 cw(c53.984,27.521) 53.899,27.436 53.842,27.492 53.786,27.549 ccw(c53.701,27.464) 53.616,27.549 53.574,27.507 ccw(c53.659,27.422) 53.574,27.337 53.687,27.224 cw(c53.602,27.139) 53.687,27.054 53.644,27.012 cw(c53.56,27.096) 53.475,27.012 ccw(c53.418,26.955) 53.362,27.012 53.1,26.75 53.1,14.05 55.15,12 55.15,10 55.825,9.325 U11.43@56.825,9.325 ; 54.041,27.973 cw(c54.125,27.888) 54.21,27.973 54.267,27.917 54.323,27.86 ccw(c54.408,27.945) 54.493,27.86 54.535,27.903 ccw(c54.451,27.987) 54.535,28.072 54.479,28.129 54.422,28.185 ; 54.422,28.186 cw(c54.507,28.27) 54.422,28.355 54.465,28.398 ; 54.465,28.398 cw(c54.55,28.313) 54.634,28.398 54.691,28.341 54.748,28.284 ccw(c54.832,28.369) 54.917,28.284 54.96,28.327 ; 54.96,28.327 ccw(c54.875,28.412) 54.96,28.497 54.903,28.553 54.847,28.61 cw(c54.931,28.695) 54.846,28.779 54.889,28.822 cw(c54.974,28.737) 55.059,28.822 55.115,28.765 55.172,28.709 ccw(c55.257,28.794) 55.341,28.709 55.384,28.751 ccw(c55.299,28.836) 55.384,28.921 ; 55.384,28.921 55.271,29.034 cw(c55.356,29.119) 55.271,29.204 55.313,29.246 cw(c55.398,29.161) 55.483,29.246 55.54,29.19 55.596,29.133 ccw(c55.681,29.218) 55.766,29.133 ; 55.766,29.133 55.808,29.175 ccw(c55.723,29.26) 55.808,29.345 55.752,29.402 55.695,29.458 cw(c55.78,29.543) 55.695,29.628 55.737,29.67 cw(c55.822,29.585) 55.907,29.67 55.964,29.614 56.02,29.557 ccw(c56.105,29.642) 56.19,29.557 ; 56.119,30.052 ccw(c56.204,29.967) 56.119,29.882 56.176,29.826 56.232,29.769 cw(c56.148,29.684) 56.232,29.6 56.19,29.557 ; 56.119,30.052 56.162,30.095 cw(c56.247,30.01) 56.331,30.095 56.388,30.038 56.445,29.981 ccw(c56.529,30.066) 56.614,29.981 56.657,30.024 ccw(c56.572,30.109) 56.657,30.194 56.6,30.25 56.544,30.307 cw(c56.628,30.392) 56.543,30.476 56.586,30.519 cw(c56.671,30.434) 56.756,30.519 56.812,30.462 56.869,30.406 ccw(c56.954,30.491) 57.038,30.406 57.081,30.448 ccw(c56.996,30.533) 57.081,30.618 57.024,30.674 56.968,30.731 cw(c57.053,30.816) 56.968,30.901 57.01,30.943 cw(c57.095,30.858) 57.18,30.943 57.237,30.887 57.293,30.83 ccw(c57.378,30.915) 57.463,30.83 57.505,30.872 ccw(c57.42,30.957) 57.505,31.042 57.449,31.099 57.392,31.155 cw(c57.477,31.24) 57.392,31.325 ; 57.392,31.325 57.435,31.367 cw(c57.519,31.283) 57.604,31.367 57.661,31.311 57.717,31.254 ccw(c57.802,31.339) 57.887,31.254 ; 57.816,31.749 ccw(c57.901,31.664) 57.816,31.58 57.873,31.523 57.93,31.466 cw(c57.845,31.382) 57.93,31.297 57.887,31.254 ; 57.816,31.749 57.859,31.792 cw(c57.944,31.707) 58.029,31.792 ccw(c58.085,31.848) 58.142,31.792 58.4,32.05 58.77,32.05 cw(c58.77,31.97) 58.85,31.97 ccw(c58.97,31.97) 58.97,31.85 59.03,31.85 ccw(c59.03,31.97) 59.15,31.97 cw(c59.23,31.97) 59.23,32.05 59.501,32.321 cw(c59.523,32.3) 59.544,32.321 ccw(c59.629,32.406) 59.714,32.321 59.756,32.364 ccw(c59.671,32.449) 59.756,32.534 cw(c59.777,32.555) 59.756,32.576 59.926,32.746 cw(c59.947,32.724) 59.968,32.746 ccw(c60.053,32.831) 60.138,32.746 60.18,32.788 ccw(c60.095,32.873) 60.18,32.958 cw(c60.201,32.979) 60.18,33 ; 60.18,33 60.35,33.17 cw(c60.371,33.149) 60.392,33.17 ccw(c60.477,33.255) 60.562,33.17 60.604,33.212 ccw(c60.52,33.297) 60.604,33.382 cw(c60.626,33.403) 60.604,33.424 60.774,33.594 cw(c60.795,33.573) 60.817,33.594 ccw(c60.901,33.679) 60.986,33.594 61.029,33.637 ccw(c60.944,33.721) 61.029,33.806 cw(c61.05,33.828) 61.029,33.849 61.198,34.018 ; 61.199,34.019 cw(c61.22,33.997) 61.241,34.018 ccw(c61.326,34.103) 61.411,34.018 61.453,34.061 ccw(c61.368,34.146) 61.453,34.231 cw(c61.474,34.252) 61.453,34.273 62,34.82 62,35.13 ccw(c61.88,35.13) 61.88,35.25 61.87,35.25 cw(c61.87,35.37) 61.75,35.37 61.75,35.43 cw(c61.87,35.43) 61.87,35.55 61.88,35.55 ccw(c61.88,35.67) 62,35.67 U8.A15@62,36
RAM_A20: U8.B14 U11.42 | length 40.9
  Top Layer w0.15: 54.56,26.993 ccw(c54.645,26.908) 54.56,26.823 54.617,26.767 54.673,26.71 cw(c54.588,26.625) 54.673,26.541 54.631,26.498 ; 54.56,26.993 54.603,27.035 cw(c54.687,26.951) 54.772,27.035 54.829,26.979 54.885,26.922 ccw(c54.97,27.007) 55.055,26.922 55.098,26.965 ccw(c55.013,27.05) 55.098,27.134 55.041,27.191 54.984,27.248 cw(c55.069,27.332) 54.984,27.417 ; 54.631,26.498 cw(c54.546,26.583) 54.461,26.498 54.405,26.555 54.348,26.611 ccw(c54.263,26.526) 54.178,26.611 54.136,26.569 ccw(c54.221,26.484) 54.136,26.399 54.192,26.342 54.249,26.286 cw(c54.164,26.201) 54.249,26.116 54.207,26.074 cw(c54.122,26.159) 54.037,26.074 53.924,26.187 ccw(c53.839,26.102) 53.754,26.187 53.712,26.144 ccw(c53.796,26.06) 53.712,25.975 cw(c53.655,25.918) 53.712,25.862 53.45,25.6 53.45,14.132 55.5,12.082 55.5,10.35 55.875,9.975 U11.42@56.825,9.975 ; 54.984,27.417 55.027,27.46 cw(c55.112,27.375) 55.197,27.46 55.253,27.403 55.31,27.347 ccw(c55.395,27.431) 55.479,27.346 55.522,27.389 ccw(c55.437,27.474) 55.522,27.559 55.465,27.615 55.409,27.672 cw(c55.494,27.757) 55.409,27.841 55.451,27.884 ; 55.451,27.884 cw(c55.536,27.799) 55.621,27.884 55.734,27.771 ccw(c55.819,27.856) 55.904,27.771 55.946,27.813 ; 55.875,28.308 55.833,28.266 ccw(c55.918,28.181) 55.833,28.096 55.89,28.04 55.946,27.983 cw(c55.861,27.898) 55.946,27.813 ; 55.876,28.308 cw(c55.96,28.223) 56.045,28.308 56.102,28.252 56.158,28.195 ccw(c56.243,28.28) 56.328,28.195 56.37,28.238 ; 56.37,28.238 ccw(c56.285,28.322) 56.37,28.407 56.314,28.464 56.257,28.52 cw(c56.342,28.605) 56.257,28.69 56.3,28.732 cw(c56.384,28.648) 56.469,28.733 56.526,28.676 56.582,28.619 ccw(c56.667,28.704) 56.752,28.619 56.795,28.662 ccw(c56.71,28.747) 56.795,28.831 56.738,28.888 56.681,28.945 cw(c56.766,29.029) 56.681,29.114 56.724,29.157 cw(c56.809,29.072) 56.894,29.157 56.95,29.1 57.007,29.044 ccw(c57.092,29.128) 57.176,29.043 57.219,29.086 ccw(c57.134,29.171) 57.219,29.256 57.162,29.312 57.106,29.369 cw(c57.191,29.454) 57.106,29.538 57.148,29.581 cw(c57.233,29.496) 57.318,29.581 57.374,29.524 57.431,29.468 ccw(c57.516,29.553) 57.601,29.468 57.643,29.51 ; 57.53,29.793 57.587,29.737 57.643,29.68 cw(c57.558,29.595) 57.643,29.51 ; 57.53,29.793 cw(c57.615,29.878) 57.53,29.963 57.572,30.005 ; 57.573,30.005 cw(c57.657,29.92) 57.742,30.005 57.799,29.949 57.855,29.892 ccw(c57.94,29.977) 58.025,29.892 58.067,29.935 ; 58.068,29.935 ccw(c57.983,30.019) 58.067,30.104 58.011,30.161 57.954,30.217 cw(c58.039,30.302) 57.954,30.387 57.997,30.43 cw(c58.082,30.345) 58.166,30.43 ; 58.166,30.43 58.223,30.373 58.28,30.316 ccw(c58.364,30.401) 58.449,30.316 58.492,30.359 ccw(c58.407,30.444) 58.492,30.528 58.379,30.642 cw(c58.463,30.727) 58.378,30.811 58.421,30.854 cw(c58.506,30.769) 58.591,30.854 58.647,30.797 58.704,30.741 ccw(c58.789,30.826) 58.873,30.741 58.916,30.783 ccw(c58.831,30.868) 58.916,30.953 58.859,31.009 58.803,31.066 cw(c58.888,31.151) 58.803,31.235 ; 58.803,31.236 58.845,31.278 cw(c58.93,31.193) 59.015,31.278 59.018,31.275 ccw(c59.071,31.329) 59.125,31.275 59.275,31.275 59.499,31.499 ccw(c59.443,31.556) 59.499,31.613 cw(c59.584,31.697) 59.499,31.782 59.542,31.825 cw(c59.627,31.74) 59.711,31.825 59.768,31.768 59.825,31.712 ccw(c59.91,31.796) 59.994,31.712 60.037,31.754 ccw(c59.952,31.839) 60.037,31.924 cw(c60.093,31.98) 60.037,32.037 62.5,34.5 62.5,36.5 U8.B14@63,37
RAM_BWN0: U8.C4 U11.93 | length 41.3
  Top Layer w0.15: U8.C4@73,38 73.05,38 73.5,37.55 73.5,35.199 75.1,33.599 75.1,33.35 75.394,33.056 cw(c75.27,32.932) 75.394,32.809 75.298,32.713 ccw(c75.422,32.589) 75.298,32.466 ccw(c75.422,32.589) 75.546,32.466 75.641,32.561 cw(c75.765,32.438) 75.889,32.561 cw(c75.765,32.438) 75.889,32.314 75.793,32.218 ccw(c75.917,32.094) 75.793,31.971 ccw(c75.917,32.094) 76.041,31.971 76.479,32.409 cw(c76.603,32.286) 76.727,32.409 cw(c76.603,32.286) 76.727,32.162 76.507,31.943 76.29,31.725 ccw(c76.414,31.602) 76.29,31.478 ccw(c76.414,31.602) 76.538,31.478 76.755,31.695 76.974,31.914 cw(c77.098,31.791) 77.222,31.914 cw(c77.098,31.791) 77.222,31.667 77.002,31.448 76.788,31.233 ccw(c76.912,31.109) 76.788,30.985 ccw(c76.912,31.109) 77.035,30.985 77.25,31.2 77.469,31.419 cw(c77.593,31.296) 77.717,31.419 cw(c77.593,31.296) 77.717,31.172 77.278,30.733 ccw(c77.402,30.609) 77.278,30.486 ccw(c77.402,30.609) 77.526,30.486 77.964,30.924 cw(c78.088,30.801) 78.212,30.924 cw(c78.088,30.801) 78.212,30.677 77.773,30.238 ccw(c77.897,30.115) 77.773,29.991 ccw(c77.897,30.115) 78.02,29.991 78.24,30.21 78.459,30.43 cw(c78.583,30.306) 78.707,30.43 cw(c78.583,30.306) 78.707,30.182 78.268,29.743 ccw(c78.392,29.62) 78.268,29.496 ccw(c78.392,29.62) 78.515,29.496 78.954,29.935 cw(c79.078,29.811) 79.202,29.935 cw(c79.078,29.811) 79.202,29.687 78.763,29.248 ccw(c78.887,29.125) 78.763,29.001 ; U11.93@78.075,12.575 79.225,12.575 80.2,13.55 80.2,28.499 79.85,28.849 79.601,28.849 79.354,29.096 ccw(c79.23,28.973) 79.106,29.096 79.01,29.001 cw(c78.887,29.125) 78.763,29.001
RAM_BWN1: U8.A4 U11.94 | length 43.6
  Top Layer w0.15: U8.A4@73,36 73,35.05 v2(74.5,33.55) ; v2@74.325,33.55 ccw(c73.903,33.55) 74.201,33.849 ccw(c74.5,34.147) v2@74.5,33.725 ; U11.94@78.075,13.225 79.125,13.225 79.95,14.05 79.95,28.1 ; v2(79.75,28.3) 79.95,28.1 ; v2@79.806,28.134 cw(c79.85,28) 79.95,28.1 ; v2@79.916,28.244 ccw(c80.05,28.2) 79.95,28.1
  Bottom Layer w0.15: v2@74.5,33.375 cw(c74.5,32.953) 74.799,33.251 cw(c75.097,33.55) v2@74.675,33.55 ; v2(74.5,33.55) 74.995,33.055 cw(c74.871,32.931) 74.995,32.807 74.89,32.702 ccw(c75.014,32.578) 74.89,32.455 ccw(c75.014,32.578) 75.138,32.455 75.595,32.912 cw(c75.719,32.789) 75.843,32.912 cw(c75.719,32.789) 75.843,32.665 75.385,32.207 ccw(c75.509,32.083) 75.385,31.96 ccw(c75.509,32.083) 75.632,31.96 75.861,32.189 76.09,32.418 cw(c76.214,32.294) 76.338,32.418 cw(c76.214,32.294) 76.338,32.17 75.88,31.712 ccw(c76.004,31.588) 75.88,31.465 ccw(c76.004,31.588) 76.127,31.465 76.585,31.923 cw(c76.709,31.799) 76.833,31.923 cw(c76.709,31.799) 76.833,31.675 76.375,31.217 ccw(c76.499,31.093) 76.375,30.97 ccw(c76.499,31.093) 76.622,30.97 77.08,31.428 cw(c77.204,31.304) 77.328,31.428 cw(c77.204,31.304) 77.328,31.18 77.099,30.951 76.87,30.722 ccw(c76.994,30.598) 76.87,30.475 ccw(c76.994,30.598) 77.117,30.475 77.575,30.933 cw(c77.699,30.809) 77.823,30.933 cw(c77.699,30.809) 77.823,30.685 77.365,30.227 ccw(c77.489,30.103) 77.365,29.98 ccw(c77.489,30.103) 77.612,29.98 78.07,30.438 cw(c78.194,30.314) 78.318,30.438 cw(c78.194,30.314) 78.318,30.19 78.089,29.961 77.86,29.732 ccw(c77.984,29.608) 77.86,29.485 ccw(c77.984,29.608) 78.107,29.485 78.565,29.943 cw(c78.689,29.819) 78.813,29.943 cw(c78.689,29.819) 78.813,29.695 78.355,29.237 ccw(c78.479,29.114) 78.355,28.99 ccw(c78.479,29.114) 78.602,28.99 79.06,29.448 cw(c79.184,29.324) 79.308,29.448 cw(c79.184,29.324) 79.308,29.2 78.85,28.742 ccw(c78.974,28.619) 78.85,28.495 ccw(c78.974,28.619) 79.097,28.495 79.203,28.6 cw(c79.326,28.476) 79.45,28.6 v2(79.75,28.3) ; v2@79.575,28.3 ccw(c79.153,28.3) 79.451,28.599 ccw(c79.75,28.897) v2@79.75,28.475
RAM_BWN2: U8.D7 U11.95 | length 44
  Top Layer w0.15: U8.D7@70,39 v1(70.5,39.5) ; v1@70.325,39.5 cw(c69.903,39.5) 70.201,39.201 cw(c70.5,38.903) v1@70.5,39.325 ; v2@72.426,36.426 cw(c72.128,36.128) 72.55,36.128 cw(c72.972,36.128) v2@72.674,36.426 ; v2(72.55,36.55) 72.5,36.5 72.55,36.45 72.55,35.7 cw(c72.425,35.7) 72.425,35.575 ccw(c72.425,35.4) 72.25,35.4 ccw(c72.425,35.4) 72.425,35.225 cw(c72.425,35.1) 72.55,35.1 72.55,34.85 72.897,34.503 cw(c72.774,34.379) 72.897,34.255 72.701,34.059 ccw(c72.825,33.935) 72.701,33.811 ccw(c72.825,33.935) 72.949,33.811 73.145,34.008 cw(c73.269,33.884) 73.392,34.008 73.61,33.79 cw(c73.504,33.684) 73.61,33.578 73.554,33.521 ccw(c73.66,33.415) 73.554,33.309 ccw(c73.66,33.415) 73.766,33.309 73.822,33.365 cw(c73.929,33.259) 74.035,33.365 cw(c73.929,33.259) 74.035,33.153 73.969,33.088 ccw(c74.075,32.982) 73.969,32.876 ccw(c74.075,32.982) 74.181,32.876 74.247,32.941 cw(c74.353,32.835) 74.459,32.941 cw(c74.353,32.835) 74.459,32.729 74.371,32.642 ccw(c74.477,32.535) 74.371,32.429 ccw(c74.477,32.535) 74.583,32.429 74.671,32.517 cw(c74.777,32.411) 74.883,32.517 cw(c74.777,32.411) 74.883,32.305 74.757,32.179 ccw(c74.863,32.073) 74.757,31.967 ccw(c74.863,32.073) 74.97,31.967 75.095,32.093 cw(c75.201,31.987) 75.307,32.093 cw(c75.201,31.987) 75.307,31.88 75.201,31.774 ccw(c75.307,31.668) 75.201,31.562 ccw(c75.307,31.668) 75.413,31.562 75.519,31.668 cw(c75.626,31.562) 75.732,31.668 cw(c75.626,31.562) 75.732,31.456 75.656,31.38 ccw(c75.762,31.274) 75.656,31.168 ccw(c75.762,31.274) 75.868,31.168 75.944,31.244 cw(c76.05,31.138) 76.156,31.244 cw(c76.05,31.138) 76.156,31.032 76.096,30.972 ccw(c76.202,30.866) 76.096,30.76 ccw(c76.202,30.866) 76.308,30.76 76.368,30.82 cw(c76.474,30.714) 76.58,30.82 cw(c76.474,30.714) 76.58,30.608 76.524,30.551 ccw(c76.63,30.445) 76.524,30.339 ccw(c76.63,30.445) 76.736,30.339 76.792,30.396 cw(c76.898,30.29) 77.004,30.396 cw(c76.898,30.29) 77.004,30.183 76.939,30.118 ccw(c77.045,30.012) 76.939,29.906 ccw(c77.045,30.012) 77.151,29.906 77.217,29.971 cw(c77.323,29.865) 77.429,29.971 cw(c77.323,29.865) 77.429,29.759 77.341,29.672 ccw(c77.447,29.566) 77.341,29.46 ccw(c77.447,29.566) 77.553,29.46 77.641,29.547 cw(c77.747,29.441) 77.853,29.547 cw(c77.747,29.441) 77.853,29.335 77.727,29.209 ccw(c77.833,29.103) 77.727,28.997 ccw(c77.833,29.103) 77.939,28.997 78.065,29.123 cw(c78.171,29.017) 78.277,29.123 cw(c78.171,29.017) 78.277,28.911 78.17,28.804 ccw(c78.276,28.698) 78.17,28.592 ccw(c78.276,28.698) 78.383,28.592 78.489,28.699 cw(c78.595,28.592) 78.701,28.699 cw(c78.595,28.592) 78.701,28.486 78.625,28.41 ccw(c78.731,28.304) 78.625,28.198 ccw(c78.731,28.304) 78.838,28.198 78.914,28.274 cw(c79.02,28.168) 79.126,28.274 cw(c79.02,28.168) 79.126,28.062 79.066,28.002 ccw(c79.172,27.896) 79.066,27.79 ccw(c79.172,27.896) 79.278,27.79 79.338,27.85 cw(c79.444,27.744) 79.55,27.85 79.7,27.7 79.7,14.45 79.125,13.875 U11.95@78.075,13.875
  Mid-Layer 2 w0.15: v1@70.5,39.325 cw(c70.5,38.903) 70.799,39.201 cw(c71.097,39.5) v1@70.675,39.5 ; v1(70.5,39.5) 71,39 71,37.3 71.75,36.55 v2(72.55,36.55) ; v2@72.426,36.426 ccw(c72.128,36.128) 72.128,36.55 ccw(c72.128,36.972) v2@72.426,36.674
RAM_BWN3: U8.A5 U11.96 | length 41.3
  Top Layer w0.15: U8.A5@72,36 72,34.75 72.4,34.35 72.4,33.55 72.865,33.085 ccw(c72.989,33.208) 73.113,33.085 73.141,33.112 cw(c73.264,32.989) 73.388,33.112 cw(c73.264,32.989) 73.388,32.865 73.237,32.713 73.085,32.562 ccw(c73.209,32.438) 73.085,32.314 ccw(c73.209,32.438) 73.333,32.314 73.484,32.466 73.636,32.617 cw(c73.759,32.494) 73.883,32.617 cw(c73.759,32.494) 73.883,32.37 73.732,32.218 73.58,32.067 ccw(c73.704,31.943) 73.58,31.82 ccw(c73.704,31.943) 73.828,31.82 74.13,32.122 cw(c74.254,31.999) 74.378,32.122 cw(c74.254,31.999) 74.378,31.875 74.075,31.572 ccw(c74.199,31.448) 74.075,31.325 ccw(c74.199,31.448) 74.323,31.325 74.474,31.476 74.625,31.627 cw(c74.749,31.504) 74.873,31.627 cw(c74.749,31.504) 74.873,31.38 74.721,31.229 74.57,31.077 ccw(c74.694,30.953) 74.57,30.83 ccw(c74.694,30.953) 74.818,30.83 74.969,30.981 75.12,31.132 cw(c75.244,31.009) 75.368,31.132 cw(c75.244,31.009) 75.368,30.885 75.065,30.582 ccw(c75.189,30.458) 75.065,30.335 ccw(c75.189,30.458) 75.312,30.335 75.464,30.486 75.615,30.638 cw(c75.739,30.514) 75.863,30.638 cw(c75.739,30.514) 75.863,30.39 75.711,30.239 75.56,30.087 ccw(c75.684,29.963) 75.56,29.84 ccw(c75.684,29.963) 75.807,29.84 75.959,29.991 76.11,30.143 cw(c76.234,30.019) 76.358,30.143 ; 76.358,30.143 cw(c76.234,30.019) 76.358,29.895 76.055,29.592 ccw(c76.179,29.468) 76.055,29.345 ccw(c76.179,29.468) 76.302,29.345 76.605,29.648 cw(c76.729,29.524) 76.853,29.648 cw(c76.729,29.524) 76.853,29.4 76.701,29.249 76.55,29.097 ccw(c76.674,28.973) 76.55,28.85 ccw(c76.674,28.973) 76.797,28.85 76.949,29.001 77.1,29.153 cw(c77.224,29.029) 77.348,29.153 cw(c77.224,29.029) 77.348,28.905 77.196,28.754 77.045,28.602 ccw(c77.169,28.478) 77.045,28.355 ccw(c77.169,28.478) 77.292,28.355 77.595,28.658 cw(c77.719,28.534) 77.843,28.658 cw(c77.719,28.534) 77.843,28.41 77.691,28.259 77.54,28.107 ccw(c77.664,27.983) 77.54,27.86 ccw(c77.664,27.983) 77.787,27.86 77.939,28.011 78.09,28.163 cw(c78.214,28.039) 78.338,28.163 cw(c78.214,28.039) 78.338,27.915 78.186,27.764 78.035,27.612 ccw(c78.159,27.488) 78.035,27.365 ccw(c78.159,27.488) 78.282,27.365 78.585,27.668 cw(c78.709,27.544) 78.833,27.668 cw(c78.709,27.544) 78.833,27.42 78.53,27.117 ccw(c78.654,26.994) 78.53,26.87 ccw(c78.654,26.994) 78.777,26.87 78.929,27.021 79.08,27.173 cw(c79.204,27.049) 79.328,27.173 cw(c79.204,27.049) 79.328,26.925 79.3,26.897 ccw(c79.424,26.774) 79.3,26.65 79.45,26.5 79.45,14.85 79.125,14.525 U11.96@78.075,14.525
RAM_CENN: U8.C3 U11.87 | length 41.6
  Top Layer w0.15: U8.C3@73.975,37.975 74.5,37.45 74.5,36.804 74.75,36.554 74.75,36.55 74.8,36.5 75.196,36.5 75.45,36.246 75.45,35.5 75.678,35.272 ccw(c75.731,35.325) 75.784,35.272 75.819,35.307 cw(c75.872,35.254) 75.926,35.307 76.032,35.201 cw(c75.979,35.148) 76.032,35.095 75.996,35.06 ccw(c76.049,35.007) 75.996,34.954 76.1,34.85 76.7,34.85 76.801,34.749 cw(c76.712,34.661) 76.801,34.573 ccw(c76.924,34.449) 76.801,34.325 ccw(c76.924,34.449) 77.048,34.325 77.136,34.414 77.225,34.502 cw(c77.349,34.378) 77.472,34.502 cw(c77.349,34.378) 77.472,34.254 77.384,34.166 77.296,34.078 ccw(c77.419,33.954) 77.296,33.83 ccw(c77.419,33.954) 77.543,33.83 77.631,33.919 77.72,34.007 cw(c77.844,33.883) 77.967,34.007 cw(c77.844,33.883) 77.967,33.759 77.879,33.671 77.791,33.583 ccw(c77.914,33.459) 77.791,33.335 ccw(c77.914,33.459) 78.038,33.335 78.126,33.424 78.215,33.512 cw(c78.339,33.388) 78.462,33.512 cw(c78.339,33.388) 78.462,33.265 78.374,33.176 78.285,33.088 ccw(c78.409,32.964) 78.285,32.84 ccw(c78.409,32.964) 78.533,32.84 78.621,32.929 78.71,33.017 cw(c78.833,32.893) 78.957,33.017 cw(c78.833,32.893) 78.957,32.77 78.78,32.593 ccw(c78.904,32.469) 78.78,32.345 ccw(c78.904,32.469) 79.028,32.345 79.116,32.434 79.205,32.522 cw(c79.328,32.398) 79.452,32.522 cw(c79.328,32.398) 79.452,32.275 79.364,32.186 79.275,32.098 ccw(c79.399,31.974) 79.275,31.85 ccw(c79.399,31.974) 79.523,31.85 79.611,31.939 79.7,32.027 cw(c79.823,31.903) 79.947,32.027 cw(c79.823,31.903) 79.947,31.78 79.859,31.691 79.77,31.603 ccw(c79.894,31.479) 79.77,31.355 ccw(c79.894,31.479) 80.018,31.355 80.106,31.444 80.195,31.532 cw(c80.318,31.408) 80.442,31.532 cw(c80.318,31.408) 80.442,31.285 80.354,31.196 80.265,31.108 ccw(c80.389,30.984) 80.265,30.86 ccw(c80.389,30.984) 80.513,30.86 cw(c80.601,30.772) 80.69,30.86 80.95,30.6 80.95,10.25 79.375,8.675 U11.87@78.075,8.675
RAM_CLK: U8.B3 U11.89 | length 43.8
  Top Layer w0.15: U8.B3@73.975,36.975 74.5,36.45 74.5,34.8 v2(76.35,32.95) ; v2@76.175,32.95 ccw(c75.753,32.95) 76.051,33.249 ccw(c76.35,33.547) v2@76.35,33.125 ; U11.89@78.075,9.975 79.225,9.975 80.45,11.2 80.45,29 ; v2(80.2,29.25) 80.45,29 ; v2@80.223,29.077 cw(c80.259,28.809) 80.45,29 ; v2@80.373,29.227 ccw(c80.641,29.191) 80.45,29
  Bottom Layer w0.15: v2(76.35,32.95) 77,32.95 cw(c77,32.925) 77.025,32.925 77.025,32.658 ccw(c77.2,32.658) 77.2,32.483 ccw(c77.2,32.658) 77.375,32.658 77.375,33.242 cw(c77.55,33.242) 77.55,33.417 cw(c77.55,33.242) 77.725,33.242 77.725,32.658 ccw(c77.9,32.658) 77.9,32.483 ccw(c77.9,32.658) 78.075,32.658 78.075,33.242 cw(c78.25,33.242) 78.25,33.417 cw(c78.25,33.242) 78.425,33.242 78.425,32.658 ccw(c78.6,32.658) 78.6,32.483 ccw(c78.6,32.658) 78.775,32.658 78.775,32.775 cw(c78.95,32.775) 78.95,32.95 79.3,32.95 79.458,32.792 ccw(c79.581,32.916) 79.705,32.792 79.788,32.875 cw(c79.911,32.751) 80.035,32.875 cw(c79.911,32.751) 80.035,32.628 79.953,32.545 ccw(c80.076,32.421) 79.953,32.297 80.2,32.05 80.2,31.8 cw(c80.025,31.8) 80.025,31.625 79.908,31.625 ccw(c79.908,31.45) 79.733,31.45 ccw(c79.908,31.45) 79.908,31.275 80.492,31.275 cw(c80.492,31.1) 80.667,31.1 cw(c80.492,31.1) 80.492,30.925 79.908,30.925 ccw(c79.908,30.75) 79.733,30.75 ccw(c79.908,30.75) 79.908,30.575 80.492,30.575 cw(c80.492,30.4) 80.667,30.4 cw(c80.492,30.4) 80.492,30.225 79.908,30.225 ccw(c79.908,30.05) 79.733,30.05 ccw(c79.908,30.05) 79.908,29.875 80.025,29.875 cw(c80.025,29.7) 80.2,29.7 v2(80.2,29.25) ; v2@76.474,32.826 cw(c76.772,32.528) 76.772,32.95 cw(c76.772,33.372) v2@76.474,33.074 ; v2@80.076,29.374 ccw(c79.778,29.672) 80.2,29.672 ccw(c80.622,29.672) v2@80.324,29.374
RAM_D00: U8.E12 U11.63 | length 44
  Top Layer w0.15: U8.E12@65,40 65.05,40 v1(65.55,39.5) v1@65.55,39.55 ; v1@65.375,39.5 ccw(c64.953,39.5) 65.251,39.799 ccw(c65.55,40.097) v1@65.55,39.675 ; U11.63@65.825,3.325 65.825,5.375 ccw(c65.825,5.525) 65.975,5.525 65.975,5.675 ccw(c65.825,5.675) 65.825,5.825 cw(c65.825,5.975) 65.675,5.975 65.675,6.125 cw(c65.825,6.125) 65.825,6.275 ccw(c65.825,6.425) 65.975,6.425 65.975,6.575 ccw(c65.825,6.575) 65.825,6.725 cw(c65.825,6.875) 65.675,6.875 65.675,7.025 cw(c65.825,7.025) 65.825,7.175 ccw(c65.825,7.325) 65.975,7.325 65.975,7.475 ccw(c65.825,7.475) 65.825,7.625 cw(c65.825,7.775) 65.675,7.775 65.675,7.925 cw(c65.825,7.925) 65.825,8.075 ccw(c65.825,8.225) 65.975,8.225 65.975,8.375 ccw(c65.825,8.375) 65.825,8.525 cw(c65.825,8.675) 65.675,8.675 65.675,8.825 cw(c65.825,8.825) 65.825,8.975 ccw(c65.825,9.125) 65.975,9.125 65.975,9.275 ccw(c65.825,9.275) 65.825,9.425 cw(c65.825,9.575) 65.675,9.575 65.675,9.725 cw(c65.825,9.725) 65.825,9.875 ccw(c65.825,10.025) 65.975,10.025 65.975,10.175 ccw(c65.825,10.175) 65.825,10.325 cw(c65.825,10.475) 65.675,10.475 65.675,10.625 cw(c65.825,10.625) 65.825,10.775 ccw(c65.825,10.925) 65.975,10.925 65.975,11.075 ccw(c65.825,11.075) 65.825,11.225 cw(c65.825,11.375) 65.675,11.375 65.675,11.525 cw(c65.825,11.525) 65.825,11.675 ccw(c65.825,11.825) 65.975,11.825 65.975,11.975 ccw(c65.825,11.975) 65.825,12.125 cw(c65.825,12.275) 65.675,12.275 65.675,12.425 cw(c65.825,12.425) 65.825,12.575 ccw(c65.825,12.725) 65.975,12.725 65.975,12.875 ccw(c65.825,12.875) 65.825,13.025 cw(c65.825,13.175) 65.675,13.175 65.675,13.325 cw(c65.825,13.325) 65.825,13.475 ccw(c65.825,13.625) 65.975,13.625 65.975,13.775 ccw(c65.825,13.775) 65.825,13.925 cw(c65.825,14.075) 65.675,14.075 65.675,14.225 cw(c65.825,14.225) 65.825,14.375 ccw(c65.825,14.525) 65.975,14.525 65.975,14.675 ccw(c65.825,14.675) 65.825,14.825 65.825,15.675 v2(66.15,16) ; v2@65.975,16 cw(c65.553,16) 65.851,15.701 cw(c66.15,15.403) v2@66.15,15.825
  MidLayer1 w0.15: v1@65.55,39.325 cw(c65.55,38.903) 65.849,39.201 cw(c66.147,39.5) v1@65.725,39.5 ; v1(65.55,39.5) 66.175,38.875 66.175,38.676 66.125,38.626 66.125,38.274 66.175,38.224 66.175,37.22 66.05,37.095 66.05,16.1 v2(66.15,16) ; 66.05,16.302 ccw(c66.452,16.302) v2@66.168,16.018 ; 66.05,16.664 ccw(c66.814,16.664) v2@66.274,16.124
RAM_D01: U8.D12 U11.62 | length 44.1
  Top Layer w0.15: U8.D12@65,39 65,38.95 v1(65.45,38.5) v1@65.5,38.5 ; U11.62@65.175,3.325 65.175,4.675 ccw(c65.175,4.825) 65.325,4.825 65.325,4.975 ccw(c65.175,4.975) 65.175,5.125 cw(c65.175,5.275) 65.025,5.275 65.025,5.425 cw(c65.175,5.425) 65.175,5.575 ccw(c65.175,5.725) 65.325,5.725 65.325,5.875 ccw(c65.175,5.875) 65.175,6.025 cw(c65.175,6.175) 65.025,6.175 65.025,6.325 cw(c65.175,6.325) 65.175,6.475 ccw(c65.175,6.625) 65.325,6.625 65.325,6.775 ccw(c65.175,6.775) 65.175,6.925 cw(c65.175,7.075) 65.025,7.075 65.025,7.225 cw(c65.175,7.225) 65.175,7.375 ccw(c65.175,7.525) 65.325,7.525 65.325,7.675 ccw(c65.175,7.675) 65.175,7.825 cw(c65.175,7.975) 65.025,7.975 65.025,8.125 cw(c65.175,8.125) 65.175,8.275 ccw(c65.175,8.425) 65.325,8.425 65.325,8.575 ccw(c65.175,8.575) 65.175,8.725 cw(c65.175,8.875) 65.025,8.875 65.025,9.025 cw(c65.175,9.025) 65.175,9.175 ccw(c65.175,9.325) 65.325,9.325 65.325,9.475 ccw(c65.175,9.475) 65.175,9.625 cw(c65.175,9.775) 65.025,9.775 65.025,9.925 cw(c65.175,9.925) 65.175,10.075 ccw(c65.175,10.225) 65.325,10.225 65.325,10.375 ccw(c65.175,10.375) 65.175,10.525 cw(c65.175,10.675) 65.025,10.675 65.025,10.825 cw(c65.175,10.825) 65.175,10.975 ccw(c65.175,11.125) 65.325,11.125 65.325,11.275 ccw(c65.175,11.275) 65.175,11.425 cw(c65.175,11.575) 65.025,11.575 65.025,11.725 cw(c65.175,11.725) 65.175,11.875 ccw(c65.175,12.025) 65.325,12.025 65.325,12.175 ccw(c65.175,12.175) 65.175,12.325 cw(c65.175,12.475) 65.025,12.475 65.025,12.625 cw(c65.175,12.625) 65.175,12.775 ccw(c65.175,12.925) 65.325,12.925 65.325,13.075 ccw(c65.175,13.075) 65.175,13.225 cw(c65.175,13.375) 65.025,13.375 65.025,13.525 cw(c65.175,13.525) 65.175,13.675 ccw(c65.175,13.825) 65.325,13.825 65.325,13.975 ccw(c65.175,13.975) 65.175,14.125 cw(c65.175,14.275) 65.025,14.275 65.025,14.425 cw(c65.175,14.425) 65.175,14.575 ccw(c65.175,14.725) 65.325,14.725 65.325,14.875 ccw(c65.175,14.875) 65.175,15.025 65.175,15.674 65.375,15.874 65.375,15.925 65.5,16.05 v2(65.55,16.05) ; 65.251,15.749 ccw(c64.95,16.05) v2@65.375,16.05 ; 65.253,15.752 cw(c65.55,15.455) v2@65.55,15.875 ; v1@65.275,38.5 ccw(c64.853,38.5) 65.151,38.799 ccw(c65.45,39.097) v1@65.45,38.675
  MidLayer1 w0.15: v2@65.426,16.174 ccw(c65.128,16.472) 65.55,16.472 ccw(c65.973,16.472) v2@65.674,16.174 ; v1@65.45,38.325 cw(c65.45,37.903) 65.749,38.201 cw(c66.047,38.5) v1@65.625,38.5 ; v1(65.45,38.5) 65.925,38.025 65.925,37.324 65.55,36.949 65.55,19.425 cw(c65.55,19.275) 65.7,19.275 65.7,19.125 cw(c65.55,19.125) 65.55,18.975 ccw(c65.55,18.825) 65.4,18.825 65.4,18.675 ccw(c65.55,18.675) 65.55,18.525 cw(c65.55,18.375) 65.7,18.375 65.7,18.225 cw(c65.55,18.225) 65.55,18.075 ccw(c65.55,17.925) 65.4,17.925 65.4,17.775 ccw(c65.55,17.775) 65.55,17.625 cw(c65.55,17.475) 65.7,17.475 65.7,17.325 cw(c65.55,17.325) 65.55,17.175 ccw(c65.55,17.025) 65.4,17.025 65.4,16.875 ccw(c65.55,16.875) 65.55,16.725 v2(65.55,16.05)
